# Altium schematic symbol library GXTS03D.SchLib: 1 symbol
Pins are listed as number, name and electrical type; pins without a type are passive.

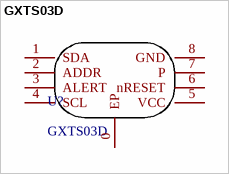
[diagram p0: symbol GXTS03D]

## GXTS03D
designator U?
footprint DFN-8_L3.0-W3.0-P0.50-BL-EP
pins: 0 EP, 1 SDA, 2 ADDR, 3 ALERT, 4 SCL, 5 VCC, 6 nRESET, 7 P, 8 GND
